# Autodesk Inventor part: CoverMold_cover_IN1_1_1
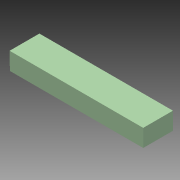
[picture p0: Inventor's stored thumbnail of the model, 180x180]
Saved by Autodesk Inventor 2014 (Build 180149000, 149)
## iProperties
Created: 2009-12
Part Number: CoverMold_cover_IN1_1_1
Document SubType Name: Modeling
Designer: gaom
Density: 1 g/cm^3
Material: Generic
Appearance: Green Pastel
Author: gaom
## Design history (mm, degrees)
node "CoverMold_cover_IN1_Base"
feature "Solid1::CoverMold_cover_IN1_Base"
tag "TaggingFeature1"
body "Solid1"
